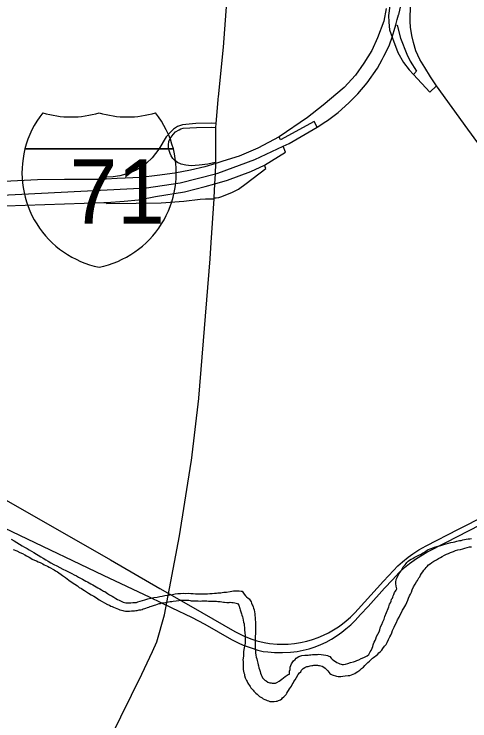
# Model space of a CAD drawing. Extents: x 0 to 96.2, y -27.5 to 31.3.
# Drawn here: x 45.317 to 46.156, y 14.912 to 16.212 of the extents above; entities that cross this region are included whole.
import ezdxf

# ---------------------------------------------------------------- set-up
doc = ezdxf.new("R2010")
doc.units = 0
for name, color, linetype in [('TB_BORDER', 7, 'Continuous'), ('TB_PP_50x10_GRID', 7, 'Continuous'), ('TB_PROF_20x5_GRID', 7, 'Continuous'), ('TB_PSDSOD', 7, 'Continuous'), ('TB_PSNSUM', 7, 'Continuous'), ('TB_SIGN_XS', 7, 'Continuous'), ('TB_SIGN_XS_GRID', 7, 'Continuous')]:
    doc.layers.add(name, color=color, linetype=linetype)

msp = doc.modelspace()

# ---------------------------------------------------------------- linework, layer by layer
at = {"layer": 'TB_BORDER'}
for points in [[(45.3112, 15.2459), (45.3166, 15.243), (45.3216, 15.24), (45.3265, 15.237), (45.3311, 15.234), (45.3357, 15.2314), (45.3403, 15.2288), (45.3445, 15.2262), (45.3487, 15.224), (45.3526, 15.2217), (45.366, 15.2135), (45.3702, 15.2113), (45.3748, 15.2083), (45.3794, 15.2057), (45.3843, 15.2027), (45.3897, 15.1998), (45.3954, 15.1968), (45.4008, 15.1938), (45.4061, 15.1912), (45.4115, 15.1886), (45.418, 15.1853), (45.423, 15.1827), (45.4272, 15.1805), (45.4314, 15.1786), (45.4352, 15.1764), (45.439, 15.1745), (45.4425, 15.1727), (45.4455, 15.1708), (45.4486, 15.1689), (45.4517, 15.1674), (45.4547, 15.166), (45.4578, 15.1637), (45.4616, 15.1622), (45.4643, 15.1604), (45.4677, 15.1585), (45.4708, 15.1567), (45.4742, 15.1548), (45.4777, 15.1526), (45.4811, 15.1507), (45.4834, 15.1496), (45.4861, 15.1481), (45.4888, 15.1459), (45.4922, 15.144), (45.4968, 15.1414), (45.5003, 15.1392)], [(46.0202, 15.1595), (46.0193, 15.1644), (46.0193, 15.1671), (46.02, 15.172), (46.0218, 15.1755), (46.0241, 15.1801), (46.0267, 15.1847), (46.0296, 15.1877), (46.0333, 15.1954), (46.0352, 15.1973), (46.0367, 15.1992), (46.0386, 15.2011), (46.0401, 15.2031), (46.0423, 15.2054), (46.0449, 15.2077), (46.048, 15.2092), (46.051, 15.2108), (46.0532, 15.2123), (46.0559, 15.2139), (46.0585, 15.2151), (46.0608, 15.2162), (46.063, 15.2174), (46.0649, 15.2182), (46.0668, 15.2193), (46.0687, 15.2205), (46.0709, 15.2217), (46.074, 15.2236), (46.0781, 15.2263), (46.0849, 15.2287), (46.0909, 15.2314), (46.0974, 15.233), (46.1027, 15.2346), (46.108, 15.2362), (46.1121, 15.2374), (46.1167, 15.2386), (46.1208, 15.2398), (46.125, 15.2406), (46.1284, 15.2414), (46.1318, 15.2422), (46.1367, 15.2434), (46.1397, 15.2438), (46.1428, 15.2446), (46.1458, 15.2454), (46.1492, 15.2462), (46.1526, 15.2466), (46.1556, 15.247), (46.1587, 15.2474)], [(46.0185, 15.0884), (46.0207, 15.093), (46.0229, 15.098), (46.0255, 15.1026), (46.0277, 15.1068), (46.0299, 15.111), (46.0318, 15.1152), (46.034, 15.119), (46.0362, 15.1225), (46.0381, 15.1255), (46.0418, 15.1339), (46.0429, 15.1374), (46.0447, 15.1416), (46.0466, 15.145), (46.0484, 15.1484), (46.0499, 15.153), (46.0521, 15.1584), (46.055, 15.1633), (46.0576, 15.1676), (46.0595, 15.1702), (46.061, 15.1725), (46.0621, 15.1748), (46.0636, 15.1771), (46.0651, 15.1798), (46.0669, 15.1829), (46.0692, 15.1863), (46.0714, 15.189), (46.0736, 15.1917), (46.0755, 15.194), (46.0774, 15.1959), (46.08, 15.199), (46.0826, 15.2009), (46.086, 15.2032), (46.0898, 15.2059), (46.0943, 15.2083), (46.0984, 15.2106), (46.1018, 15.2126), (46.1052, 15.2145), (46.109, 15.2164), (46.1131, 15.2184), (46.1165, 15.2196), (46.1203, 15.2215), (46.1256, 15.2235), (46.1297, 15.2251), (46.1339, 15.2262), (46.1384, 15.2274), (46.143, 15.2286), (46.1468, 15.2294), (46.1509, 15.2306), (46.1551, 15.2318), (46.1589, 15.2322)], [(45.3149, 15.2274), (45.3214, 15.2248), (45.3271, 15.2218), (45.3321, 15.2196), (45.3363, 15.2174), (45.3394, 15.2155), (45.342, 15.2144), (45.3443, 15.2129), (45.347, 15.2114), (45.3497, 15.2095), (45.3543, 15.2077), (45.3577, 15.2062), (45.3608, 15.2047), (45.3642, 15.2033), (45.3669, 15.2018), (45.3692, 15.2007), (45.3719, 15.1992), (45.3749, 15.1977), (45.378, 15.1962), (45.381, 15.1947), (45.3902, 15.1899), (45.3929, 15.188), (45.3964, 15.1858), (45.4056, 15.1794), (45.4109, 15.1753), (45.4171, 15.1704), (45.4232, 15.1663), (45.4286, 15.1634), (45.4332, 15.1604), (45.4366, 15.1574), (45.4404, 15.1555), (45.4431, 15.1537), (45.4462, 15.1518), (45.4496, 15.1492), (45.4538, 15.1466), (45.4584, 15.1436), (45.4634, 15.141), (45.4684, 15.138), (45.4734, 15.1346), (45.4887, 15.1261), (45.4921, 15.1246), (45.4948, 15.1231), (45.4971, 15.122), (45.4994, 15.1209), (45.5024, 15.1198), (45.5055, 15.1183), (45.5085, 15.1172), (45.5112, 15.1161), (45.5143, 15.1154), (45.5166, 15.1146), (45.5188, 15.1143), (45.5215, 15.1139), (45.5242, 15.1136), (45.5264, 15.1136), (45.5291, 15.1137), (45.5325, 15.1141), (45.5355, 15.1141), (45.5382, 15.1145), (45.5409, 15.1146), (45.5431, 15.115), (45.545, 15.1154), (45.5469, 15.1158), (45.5499, 15.1162), (45.5522, 15.117), (45.5545, 15.1178), (45.5571, 15.1186), (45.5594, 15.1193), (45.562, 15.1201), (45.5647, 15.1209), (45.567, 15.1221), (45.5696, 15.1229), (45.573, 15.1241), (45.5753, 15.1249), (45.5775, 15.1256), (45.5806, 15.1268), (45.5836, 15.1276), (45.5862, 15.128), (45.5893, 15.1288)], [(45.5003, 15.1392), (45.5037, 15.1369), (45.5068, 15.1354), (45.5098, 15.1339), (45.5125, 15.1325), (45.5152, 15.1313), (45.5175, 15.1302), (45.5201, 15.1295), (45.522, 15.1292), (45.5243, 15.1288), (45.527, 15.1288), (45.5312, 15.1289), (45.535, 15.1293), (45.5384, 15.1294), (45.5418, 15.1298), (45.5444, 15.1306), (45.5573, 15.1345), (45.5626, 15.1361), (45.5683, 15.1373), (45.5736, 15.1385), (45.58, 15.1397), (45.5849, 15.1406), (45.5895, 15.1414), (45.594, 15.1422), (45.5989, 15.143), (45.6035, 15.1438), (45.6084, 15.1446), (45.6133, 15.1455), (45.6183, 15.1459), (45.6232, 15.1463), (45.6281, 15.1468), (45.6323, 15.1464), (45.6372, 15.1465), (45.6418, 15.1462), (45.646, 15.1459), (45.6505, 15.1455), (45.6551, 15.1456), (45.6597, 15.1453), (45.6646, 15.1453), (45.6691, 15.1454), (45.6729, 15.1454), (45.6771, 15.1459), (45.6813, 15.1463), (45.6858, 15.1467), (45.6893, 15.1468), (45.6919, 15.1472), (45.6949, 15.1476), (45.6972, 15.1476), (45.6999, 15.148), (45.7029, 15.1484), (45.7056, 15.1485), (45.7078, 15.1485), (45.7146, 15.1497), (45.7207, 15.1509), (45.7268, 15.151), (45.7313, 15.1511), (45.7344, 15.1507), (45.7363, 15.1504), (45.7402, 15.1447), (45.7425, 15.1421), (45.7448, 15.1398), (45.7475, 15.1376), (45.7494, 15.1361), (45.7517, 15.1327), (45.7529, 15.1308), (45.7537, 15.1282), (45.7552, 15.1255), (45.756, 15.1236), (45.7568, 15.1217), (45.7576, 15.1191), (45.7584, 15.1161), (45.7592, 15.1126), (45.7596, 15.1088), (45.7601, 15.1058), (45.7605, 15.102), (45.7605, 15.0978), (45.761, 15.094), (45.7611, 15.0883), (45.7611, 15.0842), (45.7612, 15.0804), (45.7612, 15.0762), (45.7609, 15.072), (45.7606, 15.0674), (45.7606, 15.0633), (45.7607, 15.0587), (45.7604, 15.0534), (45.7605, 15.0484), (45.7605, 15.0446), (45.7609, 15.0416), (45.7614, 15.0367), (45.7618, 15.0325), (45.7626, 15.0291), (45.7634, 15.026), (45.7639, 15.023), (45.7647, 15.0204), (45.7654, 15.0177), (45.7662, 15.0151), (45.7667, 15.0132), (45.7675, 15.0094), (45.7683, 15.0063), (45.7695, 15.0026)], [(45.7695, 15.0026), (45.7703, 14.9995), (45.7714, 14.9965), (45.7726, 14.9938), (45.7742, 14.9912), (45.778, 14.9867), (45.7807, 14.9852), (45.7838, 14.9833), (45.7876, 14.9819), (45.7899, 14.9815), (45.7918, 14.9812), (45.7956, 14.9812), (45.7982, 14.9812), (45.8005, 14.9824), (45.8046, 14.9847), (45.8095, 14.9886), (45.8159, 14.9936), (45.8212, 14.9971), (45.8238, 14.9979), (45.8237, 15.0032), (45.8248, 15.0066), (45.8252, 15.0085), (45.8252, 15.0108), (45.8277, 15.0169), (45.8311, 15.0223), (45.8341, 15.0246), (45.8363, 15.0273), (45.8408, 15.03), (45.8465, 15.032), (45.8518, 15.0324), (45.8541, 15.0328), (45.856, 15.0329), (45.8583, 15.0329), (45.8605, 15.0333), (45.8632, 15.0333), (45.8658, 15.0337), (45.8693, 15.0342), (45.8727, 15.0342), (45.875, 15.0342), (45.8776, 15.0343), (45.8818, 15.0339), (45.8909, 15.0325), (45.8936, 15.0318), (45.8959, 15.0311), (45.8982, 15.03), (45.9005, 15.0273), (45.902, 15.0254), (45.9055, 15.0228), (45.9082, 15.021), (45.9112, 15.0195), (45.9139, 15.018), (45.9166, 15.0169), (45.9189, 15.0161), (45.9208, 15.0154), (45.9234, 15.0154), (45.9268, 15.0162), (45.9314, 15.0174), (45.9359, 15.019), (45.9416, 15.0206), (45.9454, 15.0214), (45.948, 15.0226), (45.9514, 15.0241), (45.9559, 15.0265), (45.9605, 15.0284), (45.9642, 15.0304), (45.9669, 15.0315), (45.9699, 15.0339), (45.9725, 15.0388), (45.9743, 15.0415), (45.9762, 15.0457), (45.9773, 15.0488), (45.978, 15.0514), (45.9787, 15.0537), (45.9798, 15.0568), (45.9813, 15.0595), (45.9828, 15.0625), (45.9842, 15.0671), (45.9864, 15.0713), (45.9887, 15.0755), (45.9898, 15.0793), (45.9916, 15.0847), (45.9938, 15.0889), (45.9956, 15.0938), (45.9978, 15.0988), (45.9993, 15.1041), (46.0055, 15.1187), (46.0066, 15.1217), (46.0081, 15.1267), (46.01, 15.129), (46.0107, 15.132), (46.0118, 15.1355), (46.0132, 15.1378), (46.014, 15.1397), (46.0147, 15.1416), (46.0158, 15.1442), (46.0173, 15.1477), (46.0188, 15.1504), (46.0199, 15.1523), (46.0214, 15.1546), (46.021, 15.1572), (46.0202, 15.1595)], [(45.5893, 15.1288), (45.5923, 15.1292), (45.5953, 15.1297), (45.5983, 15.1305), (45.601, 15.1309), (45.6037, 15.1313), (45.6067, 15.1317), (45.6097, 15.1321), (45.615, 15.1329), (45.62, 15.1334), (45.6237, 15.1338), (45.6275, 15.1339), (45.6348, 15.1339), (45.6382, 15.1336), (45.6405, 15.1332), (45.6427, 15.1329), (45.6454, 15.1329), (45.6496, 15.1326), (45.6526, 15.1326), (45.6557, 15.1327), (45.6591, 15.1323), (45.6625, 15.1324), (45.6651, 15.1324), (45.6682, 15.1324), (45.6712, 15.1325), (45.6743, 15.1321), (45.6773, 15.1322), (45.68, 15.1322), (45.6838, 15.1323), (45.6868, 15.1319), (45.6895, 15.1319), (45.6917, 15.1316), (45.694, 15.1312), (45.6959, 15.1313), (45.699, 15.1309), (45.7024, 15.1302), (45.7043, 15.1302), (45.7085, 15.1299), (45.7104, 15.1299), (45.7123, 15.1299), (45.7142, 15.13), (45.7176, 15.1296), (45.7202, 15.1293), (45.7229, 15.1289), (45.7252, 15.1286), (45.7282, 15.1275), (45.7306, 15.1245), (45.7322, 15.1184), (45.733, 15.1161), (45.7337, 15.1142), (45.7349, 15.1108), (45.7353, 15.1086), (45.7361, 15.1063), (45.7369, 15.1033), (45.7377, 15.1006), (45.7382, 15.0972), (45.7393, 15.0934), (45.7401, 15.0904), (45.7402, 15.0869), (45.7406, 15.0843), (45.741, 15.0809), (45.7411, 15.0782), (45.7415, 15.0752), (45.7415, 15.0725), (45.7419, 15.0702), (45.742, 15.0668), (45.742, 15.0645), (45.742, 15.0626), (45.7421, 15.06), (45.7421, 15.0581), (45.7418, 15.055), (45.7407, 15.0493), (45.74, 15.0459), (45.7393, 15.0394), (45.739, 15.0352), (45.7387, 15.0314), (45.7384, 15.0269), (45.738, 15.0238), (45.7381, 15.0212), (45.7381, 15.0181), (45.7381, 15.0151), (45.7386, 15.0064), (45.7391, 15.0033), (45.7399, 15.0003), (45.7407, 14.9976), (45.7411, 14.995), (45.7423, 14.9912), (45.7434, 14.9886), (45.7446, 14.9863), (45.7458, 14.984), (45.747, 14.9814), (45.7485, 14.9791), (45.7501, 14.9769), (45.7512, 14.975), (45.7528, 14.9727), (45.7547, 14.9704), (45.7566, 14.9682), (45.7582, 14.9663), (45.7601, 14.9644), (45.762, 14.9626), (45.7643, 14.9607)], [(45.7643, 14.9607), (45.7663, 14.9592), (45.7686, 14.9569), (45.7709, 14.9554), (45.7732, 14.9539), (45.7755, 14.9525), (45.7781, 14.9513), (45.7804, 14.9502), (45.7827, 14.9491), (45.785, 14.9484), (45.7877, 14.9477), (45.7907, 14.9473), (45.7934, 14.9474), (45.7953, 14.9474), (45.7991, 14.9478), (45.801, 14.9482), (45.8032, 14.9494), (45.8051, 14.9498), (45.807, 14.9506), (45.8093, 14.9521), (45.8111, 14.954), (45.8134, 14.956), (45.8156, 14.9583), (45.8175, 14.9606), (45.819, 14.9625), (45.8238, 14.9709), (45.8257, 14.9732), (45.8272, 14.9759), (45.8286, 14.9786), (45.8305, 14.9812), (45.832, 14.9843), (45.8342, 14.9874), (45.8364, 14.9916), (45.8394, 14.9969), (45.8424, 15.0004), (45.8443, 15.0023), (45.8461, 15.005), (45.8491, 15.0081), (45.8521, 15.01), (45.8559, 15.0116), (45.8578, 15.012), (45.8601, 15.0124), (45.862, 15.0132), (45.8646, 15.0136), (45.8665, 15.0136), (45.8684, 15.014), (45.8703, 15.014), (45.8726, 15.0141), (45.8752, 15.0141), (45.8771, 15.0137), (45.879, 15.0134), (45.8817, 15.013), (45.8836, 15.0123), (45.8867, 15.0108), (45.8893, 15.0089), (45.8924, 15.0059), (45.8944, 15.0037), (45.8963, 15.0014), (45.8982, 14.9992), (45.9001, 14.9977), (45.902, 14.9966), (45.9101, 14.994), (45.9135, 14.9937), (45.918, 14.9937), (45.9222, 14.9938), (45.9264, 14.9946), (45.9317, 14.995), (45.9351, 14.9954), (45.9381, 14.9966), (45.9411, 14.9978), (45.9438, 14.999), (45.9468, 15.0005), (45.9498, 15.0028), (45.9532, 15.0052), (45.9566, 15.0082), (45.9599, 15.0106), (45.9626, 15.0136), (45.9659, 15.0171), (45.9682, 15.0194), (45.9708, 15.0217), (45.9731, 15.0236), (45.9749, 15.0252), (45.9768, 15.0271), (45.9787, 15.0286), (45.9806, 15.0302), (45.9828, 15.0317), (45.9862, 15.0348), (45.9884, 15.0371), (45.9914, 15.0394), (45.9937, 15.0417), (45.9959, 15.0452), (45.9989, 15.049), (46.0015, 15.0521), (46.0037, 15.0559), (46.0059, 15.0613), (46.0085, 15.0662), (46.0104, 15.0697), (46.0119, 15.0739), (46.0137, 15.0781), (46.0163, 15.0842), (46.0185, 15.0884)]]:
    msp.add_lwpolyline(points, dxfattribs=at)
at = {"layer": 'TB_PP_50x10_GRID'}
for points in [[(45.271, 15.3353), (45.4942, 15.2081), (45.5852, 15.1555), (45.642, 15.1229), (45.723, 15.0761), (45.7405, 15.0674), (45.7545, 15.0619), (45.7635, 15.059), (45.777, 15.056), (45.7871, 15.0541), (45.8007, 15.053), (45.8111, 15.053), (45.821, 15.0532), (45.8328, 15.0544), (45.8437, 15.056), (45.8556, 15.0584), (45.8662, 15.0615), (45.8764, 15.0652), (45.8861, 15.0692), (45.8953, 15.0737), (45.9047, 15.079), (45.9137, 15.0846), (45.9212, 15.0903), (45.9283, 15.0959), (45.9359, 15.1024), (45.944, 15.1104), (45.9503, 15.1173), (45.9967, 15.1686), (46.0152, 15.1884), (46.0234, 15.1969), (46.0317, 15.2044), (46.0423, 15.2128), (46.051, 15.2192), (46.062, 15.2262), (46.0756, 15.2341), (46.1353, 15.2648), (46.1846, 15.2897)], [(45.2258, 15.3015), (45.3266, 15.2536), (45.4808, 15.18), (45.5662, 15.1393), (45.6069, 15.1199), (45.6435, 15.1025), (45.6677, 15.0896), (45.717, 15.0616), (45.7291, 15.0552), (45.7386, 15.0511), (45.7532, 15.0459), (45.7656, 15.0417), (45.775, 15.0397), (45.7836, 15.0387), (45.7959, 15.0377), (45.8108, 15.0373), (45.8256, 15.0383), (45.8379, 15.0396), (45.8487, 15.0418), (45.8598, 15.0445), (45.8709, 15.0481), (45.8816, 15.0524), (45.8912, 15.0569), (45.9009, 15.0621), (45.9116, 15.0688), (45.9203, 15.075), (45.9275, 15.0809), (45.9364, 15.0885), (45.9445, 15.0963), (45.9547, 15.1074), (45.9684, 15.1224), (45.9988, 15.1557), (46.0132, 15.1714), (46.0259, 15.1845), (46.0356, 15.1938), (46.045, 15.2011), (46.0574, 15.2104), (46.0765, 15.2222), (46.1128, 15.2408), (46.1951, 15.283)]]:
    msp.add_lwpolyline(points, dxfattribs=at)
at = {"layer": 'TB_PROF_20x5_GRID'}
for points in [[(46.002, 16.2223), (45.9976, 16.1991), (45.9856, 16.1685), (45.9751, 16.1454), (45.9609, 16.1221), (45.9452, 16.1), (45.9243, 16.0775), (45.886, 16.0446), (45.857, 16.0221), (45.8048, 15.9866), (45.7651, 15.9658), (45.731, 15.9511), (45.7008, 15.9416), (45.6878, 15.9375), (45.6676, 15.9312), (45.6412, 15.9251), (45.6128, 15.9194), (45.5802, 15.9152), (45.5499, 15.9114), (45.5064, 15.9095), (45.4858, 15.9086), (45.4728, 15.9081), (45.4095, 15.9081), (45.3594, 15.9076), (45.3225, 15.9057), (45.2984, 15.9043)], [(46.0085, 16.2275), (46.0063, 16.2097), (46.0068, 16.1972), (46.0081, 16.1834), (46.0127, 16.1696), (46.0132, 16.1681), (46.0231, 16.1413), (46.0336, 16.1234), (46.0442, 16.1098), (46.0522, 16.1011), (46.0819, 16.0686), (46.0946, 16.08)], [(46.0197, 16.1928), (46.0223, 16.1921), (46.0281, 16.1678), (46.0398, 16.1383), (46.0458, 16.1258), (46.0575, 16.1072), (46.0522, 16.1011)], [(45.6889, 16.0107), (45.6808, 16.0114), (45.651, 16.0107), (45.6268, 16.0085), (45.6177, 16.0052), (45.6102, 16.0004), (45.6038, 15.9946), (45.5967, 15.9865), (45.5828, 15.964), (45.5708, 15.9478), (45.5603, 15.9377), (45.5517, 15.9315), (45.5416, 15.9248), (45.5316, 15.9205), (45.522, 15.9176), (45.511, 15.9147), (45.4991, 15.9128), (45.4857, 15.9123), (45.4858, 15.9086)], [(45.8749, 16.0045), (45.8693, 16.0146), (45.8073, 15.9808), (45.8048, 15.9866)], [(45.6878, 15.9375), (45.687, 15.939), (45.6733, 15.936), (45.6574, 15.934), (45.6426, 15.9331), (45.6327, 15.9342), (45.6239, 15.9364), (45.6175, 15.9393), (45.6128, 15.9426), (45.6091, 15.9467), (45.606, 15.9513), (45.6037, 15.9558), (45.6019, 15.9612), (45.6007, 15.9663), (45.6006, 15.9717), (45.6014, 15.9776), (45.6039, 15.9834), (45.6092, 15.9907), (45.614, 15.9955), (45.6202, 15.9995), (45.6238, 16.0013), (45.628, 16.0021), (45.6522, 16.0036), (45.6799, 16.0041), (45.6883, 16.0034)], [(45.2635, 15.8585), (45.4818, 15.8656), (45.4864, 15.8659), (45.5195, 15.8679), (45.5458, 15.8708), (45.5769, 15.8764), (45.6305, 15.8854), (45.6686, 15.8952), (45.6865, 15.9002), (45.7095, 15.9065), (45.7524, 15.9225), (45.7774, 15.9343), (45.8166, 15.9582), (45.8122, 15.9693)], [(45.6848, 15.8743), (45.6884, 15.8741), (45.6935, 15.8747), (45.6992, 15.8764), (45.7186, 15.8844), (45.7295, 15.8903), (45.7437, 15.9006), (45.7799, 15.9282), (45.7774, 15.9343)], [(45.4864, 15.8659), (45.4865, 15.8639), (45.5412, 15.8645), (45.5873, 15.8651), (45.629, 15.8678), (45.6594, 15.8716), (45.6687, 15.8725), (45.681, 15.8726), (45.6847, 15.8723)]]:
    msp.add_lwpolyline(points, dxfattribs=at)
at = {"layer": 'TB_PSDSOD'}
for points in [[(46.046, 16.1989), (46.0458, 16.201), (46.0468, 16.2287), (46.0603, 16.2996), (46.0634, 16.315), (46.0775, 16.3868), (46.0813, 16.4058)], [(46.0837, 16.0969), (46.0728, 16.1137), (46.064, 16.1288), (46.0567, 16.1449), (46.052, 16.1597), (46.0493, 16.1729), (46.0468, 16.1883), (46.046, 16.1989)], [(46.2148, 15.8711), (46.2121, 15.8899), (46.2033, 15.9235), (46.1956, 15.9378), (46.1862, 15.9554), (46.1709, 15.9754), (46.1519, 16.0003), (46.0946, 16.08), (46.0837, 16.0969)]]:
    msp.add_lwpolyline(points, dxfattribs=at)
at = {"layer": 'TB_PSNSUM'}
for points in [[(46.0248, 16.2118), (46.033, 16.2473), (46.0407, 16.2825), (46.0468, 16.3179), (46.0559, 16.3721), (46.0607, 16.3978), (46.0622, 16.4055)], [(46.0004, 16.1402), (46.0082, 16.1556), (46.0127, 16.1696), (46.0168, 16.1822), (46.0197, 16.1928), (46.0223, 16.2024), (46.0246, 16.211), (46.0248, 16.2118)], [(45.8908, 16.0145), (45.8936, 16.0162), (45.9131, 16.0312), (45.9331, 16.0487), (45.9493, 16.0658), (45.9667, 16.0856), (45.9857, 16.113), (45.9943, 16.1286), (45.9976, 16.1347), (46.0004, 16.1402)], [(45.692, 15.9197), (45.76, 15.9445), (45.8122, 15.9693), (45.823, 15.9744), (45.8749, 16.0045), (45.8908, 16.0145)], [(44.7301, 15.6985), (44.7523, 15.7094), (44.7914, 15.7286), (44.8894, 15.7823), (44.9807, 15.8297), (45.0129, 15.8419), (45.0503, 15.8539), (45.0822, 15.8616), (45.1119, 15.8668), (45.1464, 15.8713), (45.1871, 15.8739), (45.2454, 15.8765), (45.5604, 15.8923), (45.6224, 15.9019), (45.6876, 15.9181), (45.692, 15.9197)]]:
    msp.add_lwpolyline(points, dxfattribs=at)
at = {"layer": 'TB_SIGN_XS'}
for points in [[(45.693, 16.0603), (45.7024, 16.1514), (45.7143, 16.3177)], [(45.6848, 15.8743), (45.6848, 15.8743), (45.6865, 15.9002), (45.6876, 15.9181), (45.6878, 15.9375), (45.6883, 16.0034), (45.6889, 16.0107), (45.6925, 16.0544), (45.6926, 16.0564), (45.693, 16.0603)], [(45.6795, 15.7921), (45.6847, 15.8723), (45.6848, 15.8743)], [(45.6567, 15.5056), (45.6776, 15.7621), (45.6795, 15.7921)], [(45.6426, 15.3876), (45.6432, 15.391), (45.6567, 15.505), (45.6567, 15.5056)], [(45.5711, 15.0394), (45.5792, 15.057), (45.5932, 15.1066), (45.6211, 15.2521), (45.6426, 15.3876)], [(45.4934, 14.879), (45.4942, 14.8805), (45.5518, 14.9977), (45.5711, 15.0394)]]:
    msp.add_lwpolyline(points, dxfattribs=at)
at = {"layer": 'TB_SIGN_XS_GRID'}
for p, q in [((45.3365, 15.9642), (45.6097, 15.9642)), ((45.6097, 15.9642), (45.3365, 15.9642)), ((45.6097, 15.9642), (45.3365, 15.9642))]:
    msp.add_line(p, q, dxfattribs=at)
for centre, start, end in [((45.5086, 15.9206), 141.669, 165.8066), ((45.4212, 16.2006), 253.0091, 286.9909), ((45.525, 16.2006), 253.0091, 286.9909), ((45.4376, 15.9206), 14.1934, 38.331), ((45.5086, 15.9206), 165.8066, 258.463), ((45.4376, 15.9206), 281.537, 14.1934)]:
    msp.add_arc(centre, 0.1776, start, end, dxfattribs=at)

# ---------------------------------------------------------------- texts
msp.add_text('71', height=0.11837, dxfattribs=at).set_placement((45.4184, 15.8266))

doc.saveas('drawing.dxf')
